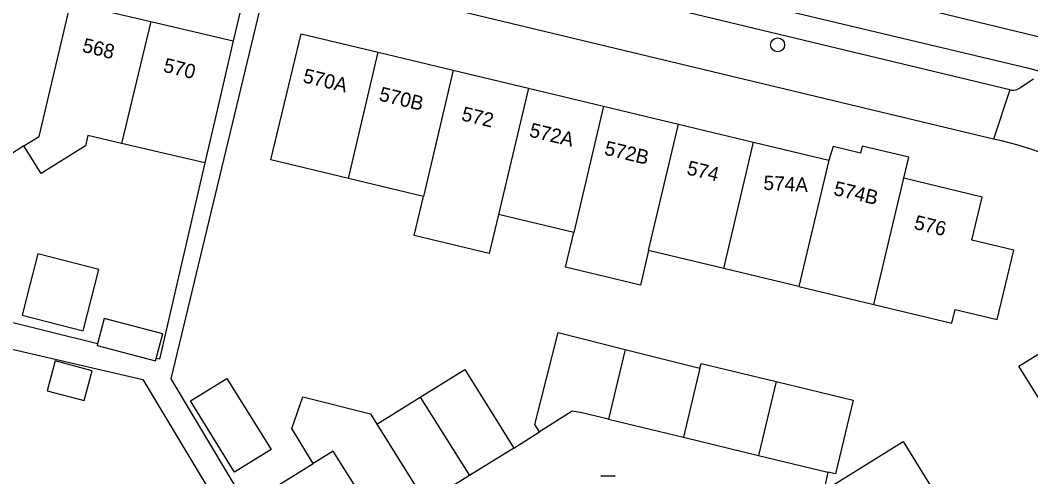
# Model space of a CAD drawing. Extents: x 157767 to 159171, y 387842 to 389425.
# Drawn here: x 158623.9 to 158694.5, y 388104.3 to 388136.2 of the extents above; entities that cross this region are included whole.
import ezdxf

# ---------------------------------------------------------------- set-up
doc = ezdxf.new("R2010")
doc.units = 0
for name, color, linetype in [('IMGEO_Boom', 7, 'Continuous'), ('IMGEO_Kolk', 7, 'Continuous'), ('IMGEO_Pand', 7, 'Continuous'), ('IMGEO_Pand_nummerreeks', 7, 'Continuous'), ('IMGEO_Rijbaan_lokaal_gesloten', 7, 'Continuous'), ('IMGEO_Rijbaan_lokaal_open', 7, 'Continuous'), ('IMGEO_Voetpad_open', 7, 'Continuous')]:
    doc.layers.add(name, color=color, linetype=linetype)

msp = doc.modelspace()

# ---------------------------------------------------------------- linework, layer by layer
at = {"layer": 'IMGEO_Boom'}
msp.add_circle((158676.844, 388134.473), 0.489, dxfattribs=at)
at = {"layer": 'IMGEO_Kolk'}
msp.add_line((158664.561, 388104.327), (158665.413, 388104.327), dxfattribs=at)
msp.add_lwpolyline([(158664.561, 388104.327), (158665.413, 388104.327)], dxfattribs=at)
for centre, start, end in [((158664.563, 388104.251), 91.55205, 178.44795), ((158664.563, 388104.251), 91.55205, 178.44795), ((158665.411, 388104.251), 1.55205, 88.44795), ((158665.411, 388104.251), 1.55205, 88.44795)]:
    msp.add_arc(centre, 0.0765, start, end, dxfattribs=at)
at = {"layer": 'IMGEO_Pand'}
for points in [[(158624.142, 388127.399), (158623.195, 388126.809), (158619.224, 388133.171), (158620.074, 388133.702), (158616.928, 388138.745)], [(158624.142, 388127.399), (158625.2, 388128.06), (158627.452, 388137.551)], [(158627.452, 388137.551), (158627.574, 388137.356), (158633.01, 388136.097)], [(158633.01, 388136.097), (158630.971, 388127.575)], [(158633.01, 388136.097), (158638.777, 388134.761)], [(158646.829, 388125.115), (158641.397, 388126.419), (158642.35, 388130.39), (158643.517, 388135.251), (158648.905, 388133.958)], [(158638.777, 388134.761), (158637.649, 388129.891), (158636.799, 388126.225)], [(158646.829, 388125.115), (158648.905, 388133.958)], [(158648.905, 388133.958), (158654.157, 388132.697)], [(158654.157, 388132.697), (158652.079, 388123.855)], [(158654.157, 388132.697), (158659.412, 388131.436)], [(158659.412, 388131.436), (158657.331, 388122.595)], [(158659.412, 388131.436), (158664.663, 388130.176)], [(158664.663, 388130.176), (158662.583, 388121.335)], [(158664.663, 388130.176), (158669.91, 388128.917)], [(158667.824, 388120.077), (158669.91, 388128.917)], [(158669.91, 388128.917), (158675.167, 388127.655)], [(158630.971, 388127.575), (158628.619, 388128.12), (158628.452, 388127.398), (158625.351, 388125.462), (158624.142, 388127.399)], [(158636.799, 388126.225), (158630.971, 388127.575)], [(158673.076, 388118.816), (158675.167, 388127.655)], [(158675.167, 388127.655), (158680.418, 388126.395)], [(158685.668, 388125.135), (158686.016, 388126.605), (158682.763, 388127.388), (158682.645, 388126.893), (158680.729, 388127.349), (158680.418, 388126.395)], [(158680.418, 388126.395), (158678.326, 388117.556)], [(158652.079, 388123.855), (158646.829, 388125.115)], [(158683.578, 388116.296), (158685.668, 388125.135)], [(158683.578, 388116.296), (158689.02, 388114.99), (158689.254, 388115.963), (158692.191, 388115.259), (158693.356, 388120.112), (158690.43, 388120.815), (158691.151, 388123.819), (158685.668, 388125.135)], [(158657.331, 388122.595), (158656.681, 388119.885), (158651.429, 388121.145), (158652.079, 388123.855)], [(158662.583, 388121.335), (158657.331, 388122.595)], [(158667.824, 388120.077), (158667.254, 388117.661), (158662.014, 388118.918), (158662.583, 388121.335)], [(158624.56, 388117.69), (158624.017, 388115.556), (158628.286, 388114.47), (158629.377, 388118.761), (158625.108, 388119.847), (158624.56, 388117.69)], [(158673.076, 388118.816), (158667.824, 388120.077)], [(158678.326, 388117.556), (158673.076, 388118.816)], [(158678.326, 388117.556), (158683.578, 388116.296)], [(158696.668, 388107.231), (158693.714, 388111.998), (158697.182, 388114.147), (158701.432, 388116.78), (158704.366, 388112.044)], [(158633.389, 388112.536), (158633.844, 388114.252), (158629.757, 388115.335), (158629.286, 388113.556)], [(158660.197, 388107.391), (158659.871, 388107.907), (158661.488, 388114.338), (158666.176, 388113.159)], [(158629.286, 388113.556), (158629.257, 388113.448), (158633.344, 388112.365), (158633.389, 388112.536)], [(158666.176, 388113.159), (158665.013, 388108.276)], [(158666.176, 388113.159), (158671.411, 388111.843)], [(158625.756, 388110.278), (158628.341, 388109.585), (158628.901, 388111.671), (158626.316, 388112.365), (158625.756, 388110.278)], [(158651.852, 388109.821), (158654.982, 388111.761), (158658.396, 388106.252)], [(158671.411, 388111.843), (158670.253, 388107.019)], [(158671.411, 388111.843), (158671.488, 388112.168), (158676.734, 388110.909)], [(158638.871, 388104.576), (158635.784, 388109.56), (158638.336, 388111.141), (158641.423, 388106.158), (158638.871, 388104.576)], [(158676.734, 388110.909), (158675.497, 388105.743)], [(158676.734, 388110.909), (158682.125, 388109.615), (158680.888, 388104.461), (158680.364, 388104.585)], [(158644.364, 388105.183), (158642.872, 388107.638), (158643.635, 388109.857), (158648.369, 388108.656), (158648.816, 388107.941)], [(158648.816, 388107.941), (158651.852, 388109.821)], [(158651.852, 388109.821), (158655.301, 388104.334)], [(158665.013, 388108.276), (158663.16, 388108.721), (158662.478, 388108.834), (158660.197, 388107.391)], [(158665.013, 388108.276), (158670.253, 388107.019)], [(158648.816, 388107.941), (158652.251, 388102.445)], [(158670.253, 388107.019), (158675.497, 388105.743)], [(158680.067, 388103.28), (158685.613, 388106.717), (158687.533, 388103.617)], [(158649.208, 388100.559), (158645.761, 388106.048), (158644.364, 388105.183)], [(158658.396, 388106.252), (158655.301, 388104.334)], [(158675.497, 388105.743), (158680.364, 388104.585)], [(158639.682, 388102.281), (158642.648, 388104.119), (158644.364, 388105.183)], [(158655.301, 388104.334), (158652.251, 388102.445)]]:
    msp.add_lwpolyline(points, dxfattribs=at)
at = {"layer": 'IMGEO_Rijbaan_lokaal_gesloten'}
for points in [[(158642.92, 388147.742), (158662.189, 388143.066), (158682.624, 388138.085), (158696.239, 388134.766)], [(158643.375, 388145.058), (158660.276, 388141.048), (158672.619, 388138.031), (158694.421, 388132.848), (158696.145, 388132.346)]]:
    msp.add_lwpolyline(points, dxfattribs=at)
at = {"layer": 'IMGEO_Rijbaan_lokaal_open'}
for points in [[(158658.396, 388106.252), (158660.197, 388107.391)], [(158680.364, 388104.585), (158680.067, 388103.28)]]:
    msp.add_lwpolyline(points, dxfattribs=at)
at = {"layer": 'IMGEO_Voetpad_open'}
for points in [[(158693.074, 388131.323), (158642.265, 388143.54)], [(158641.347, 388140.021), (158634.406, 388111.104), (158639.682, 388102.281)], [(158640.111, 388140.318), (158638.777, 388134.761)], [(158691.944, 388127.877), (158641.347, 388140.021)], [(158694.733, 388132.063), (158693.846, 388131.496)], [(158693.074, 388131.323), (158691.944, 388127.877)], [(158636.799, 388126.225), (158633.624, 388112.478), (158633.389, 388112.536)], [(158629.286, 388113.556), (158618.743, 388116.175)], [(158620.734, 388113.04), (158621.79, 388113.525), (158632.456, 388111.061), (158637.971, 388101.852)]]:
    msp.add_lwpolyline(points, dxfattribs=at)
for centre, radius, start, end in [((158693.281, 388132.207), 0.908, 256.79426, 308.46759), ((158687.98, 388108.094), 20.177, 28.49662, 78.66912)]:
    msp.add_arc(centre, radius, start, end, dxfattribs=at)

# ---------------------------------------------------------------- texts
at = {"layer": 'IMGEO_Pand_nummerreeks'}
for s, rotation, p in [('568', 346.16034, (158628.164, 388133.998)), ('570', 346.16034, (158633.826, 388132.603)), ('570A', 346.50547, (158643.59, 388131.861)), ('570B', 346.4989, (158648.91, 388130.584)), ('572', 346.50632, (158654.677, 388129.2)), ('572A', 346.50674, (158659.417, 388128.062)), ('572B', 346.50684, (158664.667, 388126.803)), ('574', 346.50097, (158670.433, 388125.419)), ('574A', 357.00257, (158675.832, 388124.335)), ('574B', 346.61571, (158680.7, 388123.984)), ('576', 346.50684, (158686.323, 388121.605))]:
    msp.add_text(s, height=1, rotation=rotation, dxfattribs=at).set_placement(p)

doc.saveas('drawing.dxf')
